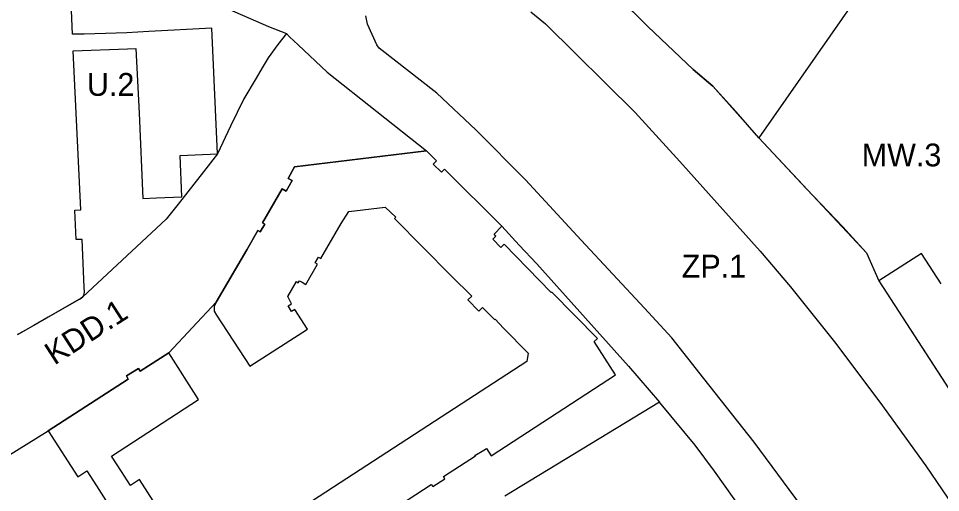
# Model space of a CAD drawing. Extents: x 7424052 to 7425705, y 5546602 to 5547569.
# Drawn here: x 7424769.6 to 7424972, y 5547332.7 to 5547436.7 of the extents above; entities that cross this region are included whole.
import ezdxf

# ---------------------------------------------------------------- set-up
doc = ezdxf.new("R2010")
doc.units = 0
for name, color, linetype in [('linie rozgraniczające', 7, 'Continuous'), ('nieprzekraczalne linie zabudowy', 7, 'Continuous'), ('obowiazujace linie zabudowy', 7, 'Continuous'), ('przeznaczenia terenów', 7, 'Continuous')]:
    doc.layers.add(name, color=color, linetype=linetype)

msp = doc.modelspace()

# ---------------------------------------------------------------- linework, layer by layer
at = {"layer": 'linie rozgraniczające'}
for p, q in [((7424907.75, 5547434.92), (7424893.17, 5547449.41)), ((7424956.07, 5547444.88), (7424932.06, 5547410.56)), ((7424814.23, 5547439.39), (7424824.51, 5547434.93)), ((7424882.08, 5547438.18), (7424885.29, 5547435.55)), ((7424846.2, 5547435.45), (7424845.86, 5547437.28)), ((7424824.51, 5547434.93), (7424828.45, 5547433.4)), ((7424848.27, 5547430.93), (7424846.2, 5547435.45)), ((7424885.29, 5547435.55), (7424904.93, 5547416.09)), ((7424917.69, 5547425.49), (7424907.75, 5547434.92)), ((7424828.45, 5547433.4), (7424826.56, 5547430.97)), ((7424828.45, 5547433.4), (7424829.13, 5547432.68)), ((7424829.13, 5547432.68), (7424831.04, 5547430.92)), ((7424826.56, 5547430.97), (7424824.43, 5547428.1)), ((7424831.04, 5547430.92), (7424837.41, 5547424.92)), ((7424848.82, 5547430.21), (7424848.27, 5547430.93)), ((7424861.45, 5547420.33), (7424848.82, 5547430.21)), ((7424824.43, 5547428.1), (7424823.12, 5547425.86)), ((7424823.12, 5547425.86), (7424821.82, 5547423.62)), ((7424837.41, 5547424.92), (7424837.41, 5547424.92)), ((7424837.41, 5547424.92), (7424859.18, 5547407.66)), ((7424921.99, 5547421.88), (7424917.69, 5547425.49)), ((7424821.82, 5547423.62), (7424819.08, 5547419.1)), ((7424927.11, 5547416.26), (7424921.99, 5547421.88)), ((7424870.02, 5547412.26), (7424861.45, 5547420.33)), ((7424819.08, 5547419.1), (7424816.18, 5547413.06)), ((7424904.93, 5547416.09), (7424914.75, 5547405.35)), ((7424932.06, 5547410.56), (7424927.11, 5547416.26)), ((7424816.18, 5547413.06), (7424813.29, 5547407.03)), ((7424880.9, 5547401.31), (7424870.02, 5547412.26)), ((7424932.06, 5547410.56), (7424942.5, 5547399.44)), ((7424830.21, 5547404.19), (7424859.18, 5547407.66)), ((7424859.18, 5547407.66), (7424861.37, 5547405.46)), ((7424813.29, 5547407.03), (7424810.26, 5547403.1)), ((7424828.85, 5547401.63), (7424830.21, 5547404.19)), ((7424861.37, 5547405.46), (7424860.66, 5547404.76)), ((7424860.66, 5547404.76), (7424860.66, 5547404.76)), ((7424860.66, 5547404.76), (7424862.44, 5547402.97)), ((7424862.44, 5547402.97), (7424863.15, 5547403.67)), ((7424863.15, 5547403.67), (7424875.67, 5547391.14)), ((7424914.75, 5547405.35), (7424932.38, 5547385.69)), ((7424810.26, 5547403.1), (7424804.65, 5547395.95)), ((7424829.72, 5547401.14), (7424828.85, 5547401.63)), ((7424828.36, 5547398.85), (7424829.72, 5547401.14)), ((7424893.14, 5547388.08), (7424880.9, 5547401.31)), ((7424823.2, 5547391.92), (7424827.53, 5547399.35)), ((7424827.53, 5547399.35), (7424828.36, 5547398.85)), ((7424942.5, 5547399.44), (7424950.51, 5547391.01)), ((7424804.65, 5547395.95), (7424802.07, 5547392.72)), ((7424802.07, 5547392.72), (7424783.77, 5547375.65)), ((7424822.69, 5547389.9), (7424823.7, 5547391.63)), ((7424823.7, 5547391.63), (7424823.2, 5547391.92)), ((7424819.73, 5547385.99), (7424822.19, 5547390.19)), ((7424822.19, 5547390.19), (7424822.69, 5547389.9)), ((7424875.67, 5547391.14), (7424879.51, 5547387.01)), ((7424950.51, 5547391.01), (7424951.9, 5547389.48)), ((7424951.9, 5547389.48), (7424955.72, 5547385.32)), ((7424907.03, 5547373.17), (7424893.14, 5547388.08)), ((7424813.02, 5547374.47), (7424819.73, 5547385.99)), ((7424879.51, 5547387.01), (7424883.36, 5547382.88)), ((7424932.38, 5547385.69), (7424939.06, 5547377.85)), ((7424955.72, 5547385.32), (7424958.41, 5547379.14)), ((7424883.36, 5547382.88), (7424903.48, 5547360.42)), ((7424939.06, 5547377.85), (7424948.66, 5547365.79)), ((7424958.41, 5547379.14), (7424988.31, 5547333.01)), ((7424783.39, 5547375.36), (7424782.41, 5547374.79)), ((7424783.77, 5547375.65), (7424783.39, 5547375.36)), ((7424782.41, 5547374.79), (7424776.14, 5547371.19)), ((7424802.63, 5547363.35), (7424813.02, 5547374.47)), ((7424913.03, 5547366.67), (7424907.03, 5547373.17)), ((7424773, 5547369.39), (7424769.87, 5547367.59)), ((7424776.14, 5547371.19), (7424773, 5547369.39)), ((7424769.87, 5547367.59), (7424769.45, 5547367.39)), ((7424920.01, 5547357.74), (7424913.03, 5547366.67)), ((7424948.66, 5547365.79), (7424958.67, 5547352.56)), ((7424796.38, 5547359.34), (7424802.63, 5547363.35)), ((7424793.33, 5547358.3), (7424795.99, 5547359.98)), ((7424795.99, 5547359.98), (7424796.38, 5547359.34)), ((7424903.48, 5547360.42), (7424910.29, 5547352.59)), ((7424776.17, 5547346.31), (7424793.73, 5547357.61)), ((7424793.73, 5547357.61), (7424793.33, 5547358.3)), ((7424931.1, 5547343.77), (7424920.01, 5547357.74)), ((7424910.29, 5547352.59), (7424876.38, 5547331.94)), ((7424918.09, 5547343.16), (7424910.29, 5547352.59)), ((7424958.67, 5547352.56), (7424968.75, 5547338.59)), ((7424767.07, 5547340.61), (7424776.17, 5547346.31)), ((7424922.33, 5547337.45), (7424918.09, 5547343.16)), ((7424943.81, 5547326.62), (7424931.1, 5547343.77)), ((7424935.47, 5547319.1), (7424922.33, 5547337.45)), ((7424968.75, 5547338.59), (7424977.79, 5547325.37))]:
    msp.add_line(p, q, dxfattribs=at)
at = {"layer": 'nieprzekraczalne linie zabudowy'}
for p, q in [((7424932.06, 5547410.56), (7424955.72, 5547385.32)), ((7424955.72, 5547385.32), (7424958.41, 5547379.14))]:
    msp.add_line(p, q, dxfattribs=at)
at = {"layer": 'obowiazujace linie zabudowy'}
for p, q in [((7424859.18, 5547407.66), (7424830.21, 5547404.19)), ((7424861.37, 5547405.46), (7424859.18, 5547407.66)), ((7424830.21, 5547404.19), (7424828.85, 5547401.63)), ((7424860.66, 5547404.76), (7424861.37, 5547405.46)), ((7424862.44, 5547402.97), (7424860.66, 5547404.76)), ((7424863.15, 5547403.67), (7424862.44, 5547402.97)), ((7424875.67, 5547391.14), (7424863.15, 5547403.67)), ((7424828.85, 5547401.63), (7424829.72, 5547401.14)), ((7424829.72, 5547401.14), (7424828.36, 5547398.85)), ((7424827.53, 5547399.35), (7424823.2, 5547391.92)), ((7424828.36, 5547398.85), (7424827.53, 5547399.35)), ((7424840.48, 5547391.72), (7424842.12, 5547394.34)), ((7424842.12, 5547394.34), (7424850.11, 5547395.33)), ((7424850.11, 5547395.33), (7424852.41, 5547393.13)), ((7424823.7, 5547391.63), (7424822.69, 5547389.9)), ((7424823.2, 5547391.92), (7424823.7, 5547391.63)), ((7424835.98, 5547384.07), (7424840.48, 5547391.72)), ((7424852.41, 5547393.13), (7424852.14, 5547392.86)), ((7424852.14, 5547392.86), (7424864.6, 5547380.28)), ((7424822.19, 5547390.19), (7424819.73, 5547385.99)), ((7424822.69, 5547389.9), (7424822.19, 5547390.19)), ((7424873.99, 5547389.42), (7424875.67, 5547391.14)), ((7424873.71, 5547388.31), (7424874.41, 5547389)), ((7424875.47, 5547386.49), (7424873.71, 5547388.31)), ((7424874.41, 5547389), (7424873.99, 5547389.42)), ((7424819.73, 5547385.99), (7424813.02, 5547374.47)), ((7424876.19, 5547387.21), (7424875.47, 5547386.49)), ((7424886.54, 5547376.6), (7424876.19, 5547387.21)), ((7424834.74, 5547383.11), (7424835.49, 5547384.36)), ((7424835.49, 5547384.36), (7424835.98, 5547384.07)), ((7424832.72, 5547378.38), (7424835.22, 5547382.79)), ((7424835.22, 5547382.79), (7424834.74, 5547383.11)), ((7424864.6, 5547380.28), (7424869.09, 5547375.78)), ((7424828.72, 5547375.75), (7424830.62, 5547378.99)), ((7424830.62, 5547378.99), (7424831.04, 5547378.74)), ((7424831.04, 5547378.74), (7424831.33, 5547379.2)), ((7424831.33, 5547379.2), (7424831.9, 5547378.86)), ((7424831.9, 5547378.86), (7424832.72, 5547378.38)), ((7424829.55, 5547374.11), (7424828.72, 5547375.75)), ((7424869.09, 5547375.78), (7424868.22, 5547374.98)), ((7424886.68, 5547376.71), (7424886.54, 5547376.6)), ((7424896.67, 5547366.51), (7424886.68, 5547376.71)), ((7424812.58, 5547373.51), (7424812.56, 5547372.54)), ((7424813.02, 5547374.47), (7424812.58, 5547373.51)), ((7424828.81, 5547373.67), (7424829.55, 5547374.11)), ((7424829.52, 5547372.47), (7424828.81, 5547373.67)), ((7424868.22, 5547374.98), (7424870.64, 5547372.5)), ((7424870.64, 5547372.5), (7424871.49, 5547373.35)), ((7424871.49, 5547373.35), (7424874.11, 5547370.66)), ((7424812.56, 5547372.54), (7424813.06, 5547371.66)), ((7424813.06, 5547371.66), (7424820.4, 5547360.43)), ((7424830.27, 5547372.91), (7424829.52, 5547372.47)), ((7424833.05, 5547368.55), (7424830.27, 5547372.91)), ((7424874.11, 5547370.66), (7424874.21, 5547370.77)), ((7424874.21, 5547370.77), (7424876.08, 5547368.78)), ((7424820.4, 5547360.43), (7424833.05, 5547368.55)), ((7424876.08, 5547368.78), (7424881.5, 5547363.28)), ((7424895.97, 5547365.84), (7424896.67, 5547366.51)), ((7424900.66, 5547358.56), (7424895.97, 5547365.84)), ((7424802.63, 5547363.35), (7424796.38, 5547359.34)), ((7424809.13, 5547353.16), (7424802.63, 5547363.35)), ((7424881.5, 5547363.28), (7424881.21, 5547361.51)), ((7424881.21, 5547361.51), (7424863.83, 5547350.2)), ((7424795.99, 5547359.98), (7424793.33, 5547358.3)), ((7424796.38, 5547359.34), (7424795.99, 5547359.98)), ((7424793.73, 5547357.61), (7424776.17, 5547346.31)), ((7424793.33, 5547358.3), (7424793.73, 5547357.61)), ((7424873.36, 5547340.82), (7424900.66, 5547358.56)), ((7424790.04, 5547340.71), (7424809.13, 5547353.16)), ((7424863.83, 5547350.2), (7424803.91, 5547311.34)), ((7424776.17, 5547346.31), (7424782.68, 5547336.19)), ((7424869.81, 5547340.9), (7424871.77, 5547342.03)), ((7424869.89, 5547340.78), (7424869.81, 5547340.9)), ((7424871.77, 5547342.03), (7424872.35, 5547342.37)), ((7424872.35, 5547342.37), (7424873.36, 5547340.82)), ((7424792.23, 5547337.33), (7424790.04, 5547340.71)), ((7424862.9, 5547336.26), (7424869.89, 5547340.78)), ((7424782.68, 5547336.19), (7424784.67, 5547337.47)), ((7424784.67, 5547337.47), (7424786.74, 5547334.23)), ((7424794.2, 5547334.28), (7424792.23, 5547337.33)), ((7424796.23, 5547335.59), (7424794.2, 5547334.28)), ((7424802.68, 5547325.47), (7424796.23, 5547335.59)), ((7424860.54, 5547334.03), (7424863.21, 5547335.77)), ((7424863.21, 5547335.77), (7424862.9, 5547336.26)), ((7424786.74, 5547334.23), (7424788.81, 5547331)), ((7424848.3, 5547326.8), (7424860.23, 5547334.52)), ((7424860.23, 5547334.52), (7424860.54, 5547334.03))]:
    msp.add_line(p, q, dxfattribs=at)
for points in [[(7424963.39, 5547464.82), (7424952.32, 5547465.95), (7424941.27, 5547466.94), (7424922.3, 5547469.68), (7424922.22, 5547469.17), (7424901.48, 5547471.82), (7424901.61, 5547472.67), (7424885.29, 5547474.96), (7424885.19, 5547474), (7424870.11, 5547476.25), (7424866.11, 5547467.66), (7424879.21, 5547455.87), (7424882.69, 5547452.8), (7424887.55, 5547448.67), (7424890.38, 5547452.05), (7424893.17, 5547449.41), (7424907.75, 5547434.92), (7424917.69, 5547425.49), (7424921.99, 5547421.88), (7424932.06, 5547410.56)], [(7424769.45, 5547367.39), (7424769.87, 5547367.59), (7424782.41, 5547374.79), (7424783.06, 5547375.17), (7424783.39, 5547375.36), (7424783.77, 5547375.65), (7424783.97, 5547375.95), (7424784.08, 5547376.29), (7424784.12, 5547376.71), (7424784.07, 5547377.79), (7424783.65, 5547388.27), (7424782.32, 5547388.22), (7424782.02, 5547394.67), (7424783.3, 5547394.71), (7424781.66, 5547429.6), (7424793.54, 5547430.08), (7424795.42, 5547430.12), (7424796.16, 5547415.96), (7424796.96, 5547397.21), (7424799.91, 5547397.37), (7424805.51, 5547397.59), (7424805.11, 5547406.63), (7424813.29, 5547407.03), (7424812.07, 5547434.58), (7424798.27, 5547433.88), (7424793.39, 5547433.54), (7424784.09, 5547433.23), (7424781.49, 5547433.3), (7424781.25, 5547438.42)], [(7424972.11, 5547378.49), (7424967.81, 5547385.17), (7424958.41, 5547379.14)], [(7424958.41, 5547379.14), (7424988.31, 5547333.01)]]:
    msp.add_lwpolyline(points, dxfattribs=at)

# ---------------------------------------------------------------- texts
at = {"layer": 'przeznaczenia terenów'}
for s, p in [('U.2', (7424784.67, 5547419.74)), ('MW.3', (7424954.67, 5547404.27)), ('ZP.1', (7424915.18, 5547379.9))]:
    msp.add_text(s, height=5, dxfattribs=at).set_placement(p)
msp.add_text('KDD.1', height=5, rotation=32.8177, dxfattribs=at).set_placement((7424777.52, 5547360.55))

doc.saveas('drawing.dxf')
